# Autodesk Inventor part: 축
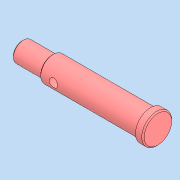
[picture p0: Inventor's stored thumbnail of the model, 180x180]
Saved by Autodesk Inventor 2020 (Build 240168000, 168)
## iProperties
Created: 2025-01
Part Number: 축
Material: 강철, 탄소
Document SubType Name: Modeling
Designer: 1강의실14
Density: 7.85 g/cm^3
Appearance: 기본값
Author: jhkim
Sending System: Autodesk Inventor 2025
Preprocessor: ST-DEVELOPER v20
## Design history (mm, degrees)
feature "솔리드1"
node "솔리드2"
